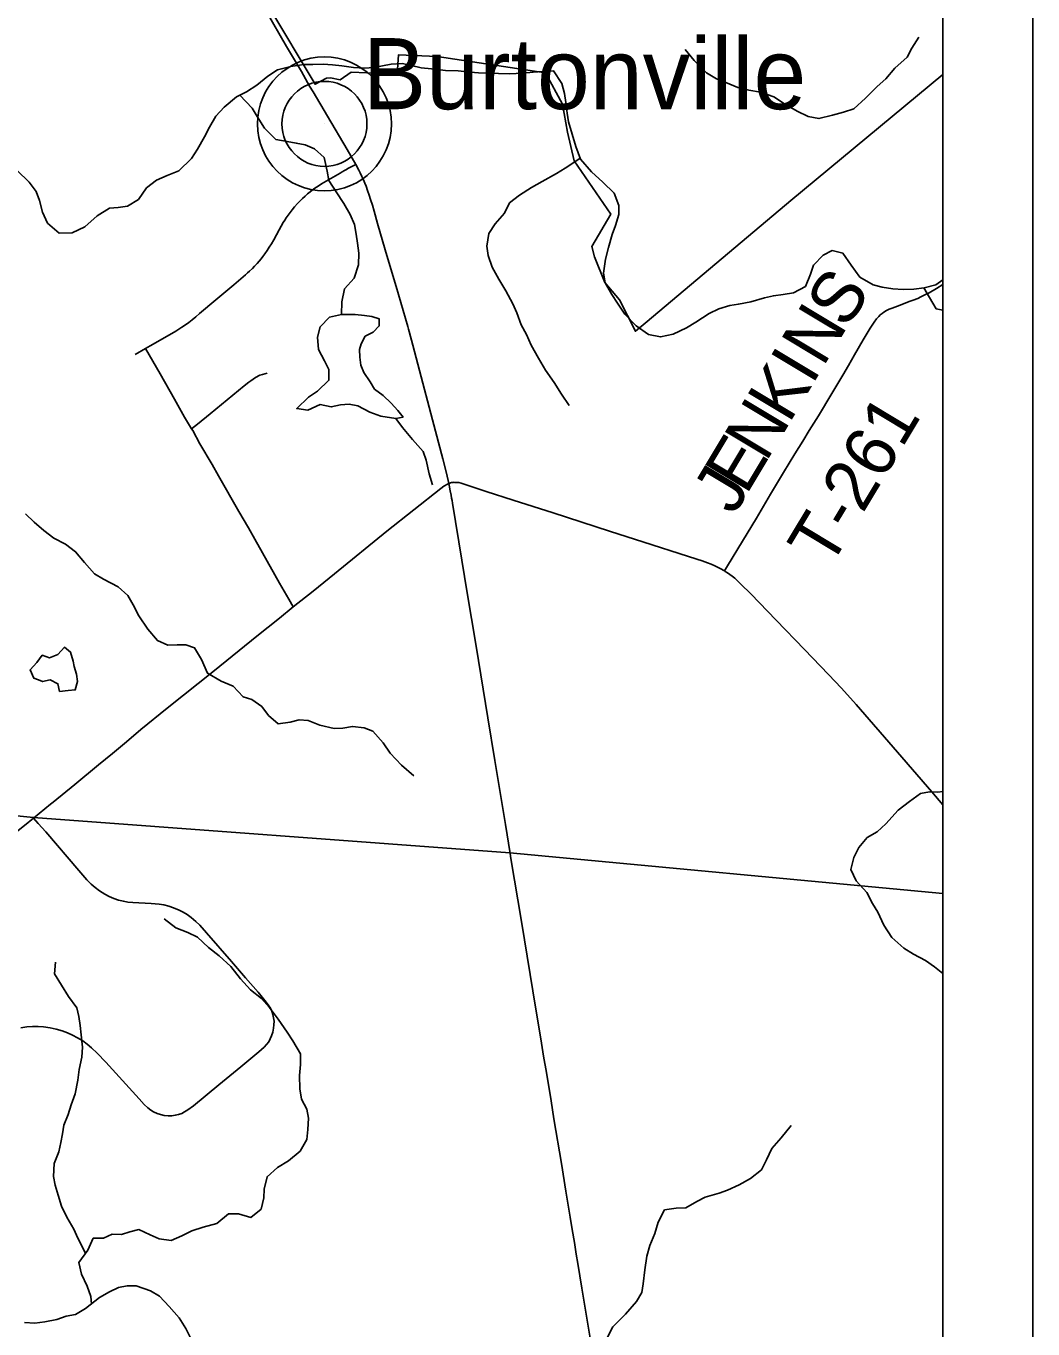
# Model space of a CAD drawing. Extents: x 0 to 34, y 0 to 22.
# Drawn here: x 7.881 to 9, y 18.658 to 20.107 of the extents above; entities that cross this region are included whole.
import ezdxf

# ---------------------------------------------------------------- set-up
doc = ezdxf.new("R2010")
doc.units = 0
for name, color, linetype in [('Default', 7, 'Continuous'), ('GM_X_County_Road', 7, 'Continuous'), ('GM_X_Major_River', 7, 'Continuous'), ('GM_X_Minor_Lake', 7, 'Continuous'), ('GM_X_Minor_River', 7, 'Continuous'), ('GM_X_State_Route', 7, 'Continuous'), ('GM_X_Township_Road', 7, 'Continuous'), ('GM_X_Township_Road_Text', 7, 'Continuous'), ('GM_X_Unincorporated', 7, 'Continuous'), ('GM_X_Unincorporated_Location', 7, 'Continuous'), ('GM_X_Unincorporated_Text', 7, 'Continuous'), ('SH_Data', 7, 'Continuous')]:
    doc.layers.add(name, color=color, linetype=linetype)

msp = doc.modelspace()

# ---------------------------------------------------------------- linework, layer by layer
at = {"layer": 'Default'}
msp.add_lwpolyline([(8.1505, 20.1279), (8.202, 20.0419), (8.2145, 20.0487), (8.2191, 20.0491), (8.2297, 20.0468), (8.2421, 20.0552), (8.2768, 20.0539), (8.2931, 20.0532), (8.2947, 20.0744), (8.3378, 20.0728), (8.458, 20.0544), (8.4769, 20.0198), (8.4824, 19.9885), (8.4901, 19.9569), (8.5306, 19.8974), (8.5095, 19.8617), (8.5125, 19.8499), (8.5241, 19.8214), (8.5403, 19.8021), (8.5581, 19.7674), (8.571, 19.7782), (8.7307, 19.9126), (8.9, 20.0527), (8.9, 20.9)], dxfattribs=at)
at = {"layer": 'GM_X_County_Road'}
for points in [[(8.657, 19.5011), (8.6524, 19.5037), (8.6494, 19.5051), (8.6462, 19.5067), (8.6422, 19.5083), (8.6381, 19.51), (8.6321, 19.5121), (8.6264, 19.5141), (8.6069, 19.5204), (8.5767, 19.5301), (8.5294, 19.5453), (8.4667, 19.5654), (8.4223, 19.5797), (8.3921, 19.5893), (8.3643, 19.5985), (8.3619, 19.5991), (8.3599, 19.5993), (8.3575, 19.5994), (8.3565, 19.5995), (8.3554, 19.5994), (8.3536, 19.5992), (8.3505, 19.5982)], [(8.9, 19.2409), (8.8876, 19.2553), (8.8493, 19.2994), (8.8033, 19.3524), (8.7871, 19.3705), (8.7727, 19.386), (8.7461, 19.4138), (8.7144, 19.4463), (8.6864, 19.4754), (8.6754, 19.4864), (8.6717, 19.4898), (8.6685, 19.4928), (8.6656, 19.4951), (8.6631, 19.497), (8.6605, 19.4988), (8.6579, 19.5005), (8.657, 19.5011)]]:
    msp.add_lwpolyline(points, dxfattribs=at)
at = {"layer": 'GM_X_Major_River'}
for points in [[(7.8707, 19.9461), (7.8841, 19.9329), (7.8919, 19.9228), (7.8958, 19.9125), (7.8989, 19.8998), (7.9047, 19.8876), (7.9174, 19.8763), (7.9318, 19.8767), (7.946, 19.8833), (7.9596, 19.8955), (7.9734, 19.904), (7.9829, 19.9049), (7.9936, 19.9062), (8.0055, 19.9139), (8.0145, 19.9267), (8.0257, 19.9352), (8.0376, 19.9406), (8.0506, 19.9457), (8.0646, 19.9595), (8.0713, 19.9696), (8.0792, 19.9835), (8.0847, 19.994), (8.0918, 20.0064), (8.1008, 20.0165), (8.1147, 20.028), (8.1258, 20.0334), (8.1374, 20.0408), (8.1494, 20.0508), (8.1601, 20.0578), (8.175, 20.0617), (8.1895, 20.0637), (8.1994, 20.0638), (8.2108, 20.064), (8.2214, 20.0634), (8.2316, 20.0624), (8.2448, 20.0606), (8.2573, 20.0596), (8.2669, 20.0605), (8.2768, 20.0622), (8.2867, 20.0643), (8.2988, 20.0648), (8.309, 20.0627), (8.32, 20.0601), (8.3313, 20.0588), (8.3469, 20.0573), (8.3609, 20.0566), (8.3708, 20.0557), (8.3836, 20.0546), (8.3935, 20.054), (8.4182, 20.0535), (8.433, 20.054), (8.4444, 20.0552), (8.4547, 20.0562), (8.4672, 20.0567), (8.4764, 20.0428), (8.4792, 20.0317), (8.4808, 20.0214), (8.4821, 20.0096), (8.4838, 20), (8.4877, 19.9863), (8.4919, 19.9725), (8.4969, 19.9587), (8.5091, 19.9444), (8.5218, 19.9331), (8.5344, 19.9207), (8.5398, 19.9072), (8.5396, 19.897), (8.5359, 19.8849), (8.5323, 19.8747), (8.5282, 19.8603), (8.5249, 19.8475), (8.5226, 19.832), (8.5243, 19.8213), (8.532, 19.8082)], [(8.532, 19.8082), (8.5382, 19.7986), (8.5463, 19.7862), (8.5589, 19.7734), (8.5728, 19.7636), (8.586, 19.761), (8.6001, 19.7642), (8.6147, 19.7711), (8.6251, 19.7773), (8.6401, 19.7869), (8.6508, 19.7924), (8.663, 19.7959), (8.6726, 19.7976), (8.6863, 19.8), (8.7016, 19.8046), (8.7115, 19.8067), (8.7225, 19.8083), (8.7339, 19.81), (8.747, 19.817), (8.7526, 19.8309), (8.7559, 19.8407), (8.7668, 19.8519), (8.7767, 19.857), (8.7888, 19.8541), (8.798, 19.8406), (8.8076, 19.8275), (8.8222, 19.8188), (8.8324, 19.8163), (8.8441, 19.8145), (8.8559, 19.8139), (8.8676, 19.814), (8.8791, 19.8157), (8.892, 19.8188), (8.9, 19.8243)]]:
    msp.add_lwpolyline(points, dxfattribs=at)
at = {"layer": 'GM_X_Minor_Lake'}
for points in [[(8.2314, 19.786), (8.2181, 19.7831), (8.2078, 19.7722), (8.2046, 19.7608), (8.2059, 19.7471), (8.2126, 19.7345), (8.2171, 19.725), (8.2173, 19.7128), (8.2046, 19.7008), (8.1947, 19.6941), (8.1816, 19.6813), (8.1938, 19.6797), (8.2075, 19.686), (8.22, 19.6832), (8.2303, 19.6857), (8.2398, 19.6863), (8.2496, 19.6843), (8.2628, 19.6773), (8.2749, 19.673), (8.2916, 19.6702)], [(8.2916, 19.6702), (8.2999, 19.672), (8.294, 19.6793), (8.2865, 19.6873), (8.2778, 19.6958), (8.2681, 19.7031), (8.2632, 19.7112), (8.2561, 19.7215), (8.2528, 19.7295), (8.2518, 19.7386), (8.2515, 19.747), (8.2531, 19.7534), (8.2577, 19.7617), (8.2665, 19.7662), (8.2734, 19.7733), (8.2732, 19.7813), (8.2652, 19.7837), (8.2569, 19.7849), (8.2466, 19.7858), (8.2314, 19.786)], [(7.9341, 19.3947), (7.9331, 19.4008), (7.9302, 19.4107), (7.9234, 19.4161), (7.9161, 19.4082), (7.9069, 19.4045), (7.8986, 19.4073), (7.8928, 19.3993), (7.8851, 19.3911), (7.8892, 19.3819), (7.8946, 19.3798)], [(7.8946, 19.3798), (7.899, 19.378), (7.9074, 19.3798), (7.9161, 19.3755), (7.9179, 19.3671), (7.9274, 19.3682), (7.9353, 19.3688), (7.9377, 19.3779), (7.9367, 19.3863), (7.9341, 19.3947)]]:
    msp.add_lwpolyline(points, dxfattribs=at)
at = {"layer": 'GM_X_Minor_River'}
for points in [[(8.8732, 20.0941), (8.8655, 20.0818), (8.8601, 20.072), (8.8466, 20.0596), (8.8366, 20.048), (8.827, 20.0393), (8.814, 20.0262), (8.8009, 20.0146), (8.7895, 20.0109), (8.7773, 20.0076), (8.7621, 20.0036), (8.7503, 20.006), (8.7379, 20.0119), (8.7239, 20.02), (8.7119, 20.0278), (8.6971, 20.0329), (8.6842, 20.0353), (8.6721, 20.0381), (8.6585, 20.0439), (8.6483, 20.0479), (8.637, 20.0544), (8.6235, 20.0683), (8.6134, 20.0805)], [(8.1183, 20.0298), (8.1321, 20.0154), (8.1377, 20.0059), (8.1459, 19.9932), (8.1582, 19.9805), (8.1711, 19.9781), (8.181, 19.9765), (8.1908, 19.9745), (8.2014, 19.9702), (8.2119, 19.9606), (8.2155, 19.9453), (8.2173, 19.935), (8.2255, 19.9224), (8.2341, 19.9094), (8.2411, 19.8972), (8.2459, 19.8861), (8.2477, 19.8754), (8.2491, 19.8652), (8.2505, 19.8541), (8.2503, 19.8412), (8.2456, 19.8265), (8.2348, 19.8144), (8.2316, 19.8), (8.2314, 19.786)], [(8.4966, 19.9597), (8.4897, 19.9547), (8.4801, 19.9484), (8.4702, 19.9428), (8.4545, 19.9338), (8.4427, 19.9271), (8.4293, 19.9186), (8.4182, 19.9099), (8.4127, 19.8986), (8.4023, 19.8866), (8.395, 19.876), (8.3929, 19.862), (8.3943, 19.8517), (8.3987, 19.8384), (8.4062, 19.8254), (8.414, 19.8124), (8.4218, 19.7978), (8.4262, 19.7879), (8.431, 19.7746), (8.4369, 19.7639), (8.4421, 19.752), (8.4503, 19.7375), (8.4581, 19.7241), (8.4678, 19.7103), (8.476, 19.6973), (8.4846, 19.6847)], [(8.8786, 19.8156), (8.885, 19.8047), (8.8924, 19.7924), (8.9, 19.7908)], [(8.2916, 19.6702), (8.299, 19.6602), (8.3103, 19.6472), (8.3223, 19.6337), (8.3256, 19.6242), (8.3288, 19.609), (8.3325, 19.5968)], [(7.88, 19.5644), (7.8897, 19.5551), (7.9003, 19.5459), (7.9115, 19.5374), (7.9244, 19.5308), (7.9357, 19.5223), (7.9458, 19.5104), (7.9566, 19.4978), (7.9668, 19.4919), (7.983, 19.4834), (7.9939, 19.4738), (7.9999, 19.4631), (8.0062, 19.4512), (8.0159, 19.4363), (8.0267, 19.4236), (8.0384, 19.4186), (8.0487, 19.4188), (8.0582, 19.4187), (8.068, 19.4156), (8.0758, 19.4026), (8.0825, 19.3873), (8.0975, 19.3784), (8.1111, 19.3729), (8.122, 19.361), (8.1318, 19.3579), (8.1428, 19.3501), (8.1502, 19.3402), (8.1608, 19.3309), (8.1744, 19.3327), (8.1843, 19.3356), (8.1942, 19.3347), (8.2074, 19.3296), (8.2233, 19.326), (8.2328, 19.3263), (8.2435, 19.3281), (8.2564, 19.3264), (8.2662, 19.3229), (8.2778, 19.3098), (8.2853, 19.2984), (8.298, 19.2849), (8.3119, 19.2734)], [(8.9, 19.2557), (8.8944, 19.2549), (8.8849, 19.2554), (8.875, 19.2536), (8.8627, 19.2446), (8.8501, 19.2349), (8.8366, 19.2198), (8.827, 19.2108), (8.8156, 19.2045), (8.8063, 19.1936), (8.8009, 19.1823), (8.7977, 19.169), (8.8036, 19.1564), (8.8152, 19.1437), (8.8215, 19.1315), (8.8275, 19.1216), (8.8341, 19.1074), (8.8431, 19.0936), (8.8566, 19.0817), (8.8672, 19.0751), (8.8804, 19.0681), (8.8905, 19.0608), (8.9, 19.0536)], [(7.9535, 18.6865), (7.9527, 18.6944), (7.9487, 18.7062), (7.9424, 18.7192), (7.9392, 18.7325), (7.9492, 18.7461), (7.9554, 18.7593), (7.9668, 18.7592), (7.9764, 18.764), (7.9866, 18.7635), (7.9961, 18.7664), (8.006, 18.769), (8.0185, 18.7631), (8.0287, 18.7588), (8.0419, 18.7568), (8.0538, 18.762), (8.0648, 18.7675), (8.0774, 18.7716), (8.0926, 18.7756), (8.1057, 18.7864), (8.1167, 18.7863), (8.1307, 18.7824), (8.1422, 18.7917), (8.145, 18.8042), (8.1455, 18.8137), (8.1487, 18.8277), (8.1602, 18.8379), (8.1724, 18.8453), (8.1855, 18.8562), (8.1928, 18.869), (8.1941, 18.88), (8.1946, 18.8929), (8.1929, 18.9028), (8.1869, 18.9139), (8.1851, 18.9253), (8.1846, 18.9402), (8.1858, 18.9523), (8.1856, 18.9641), (8.1771, 18.9786), (8.1711, 18.9885), (8.161, 19.0027), (8.1509, 19.0161), (8.1423, 19.0257), (8.1303, 19.0354), (8.119, 19.0476), (8.1082, 19.0614), (8.0954, 19.073), (8.0834, 19.0826), (8.0714, 19.0938), (8.0604, 19.0992), (8.0472, 19.1043), (8.0344, 19.1143)], [(7.9466, 18.7426), (7.9383, 18.7595), (7.9339, 18.7694), (7.9261, 18.7828), (7.9202, 18.795), (7.9165, 18.8072), (7.9132, 18.8183), (7.9111, 18.8278), (7.912, 18.8422), (7.9171, 18.8555), (7.9195, 18.8657), (7.9211, 18.8752), (7.9228, 18.885), (7.9274, 18.8968), (7.931, 18.9074), (7.9353, 18.9198), (7.9381, 18.935), (7.9398, 18.9468), (7.9426, 18.9604), (7.9435, 18.9718), (7.9418, 18.9855), (7.9408, 18.9957), (7.9394, 19.0056), (7.9372, 19.0152), (7.9279, 19.0278), (7.9122, 19.0531), (7.9135, 19.066)], [(8.5257, 18.6464), (8.5331, 18.6607), (8.5469, 18.675), (8.5593, 18.6889), (8.5651, 18.6991), (8.5667, 18.7086), (8.5684, 18.7242), (8.5709, 18.7393), (8.5741, 18.7514), (8.5795, 18.7647), (8.5835, 18.7772), (8.5905, 18.7908), (8.6034, 18.7929), (8.614, 18.7931), (8.6263, 18.8002), (8.6358, 18.805), (8.651, 18.8094), (8.6606, 18.8127), (8.6735, 18.8187), (8.6862, 18.8257), (8.6984, 18.8355), (8.7039, 18.8464), (8.7097, 18.8589), (8.7201, 18.8709), (8.7313, 18.8845)], [(7.8791, 18.6656), (7.8905, 18.6651), (7.9015, 18.6665), (7.9149, 18.669), (7.9252, 18.6727), (7.9358, 18.6744), (7.9469, 18.6811), (7.9622, 18.6935), (7.9733, 18.6998), (7.9836, 18.7047), (7.9931, 18.7064), (8.003, 18.7063), (8.0189, 18.7008), (8.0291, 18.695), (8.0399, 18.6835), (8.0508, 18.6708), (8.0582, 18.659), (8.0638, 18.6479)]]:
    msp.add_lwpolyline(points, dxfattribs=at)
at = {"layer": 'GM_X_State_Route'}
for points in [[(8.3505, 19.5982), (8.348, 19.6095), (8.344, 19.6257), (8.3326, 19.669), (8.318, 19.7236), (8.3106, 19.7519), (8.3066, 19.767), (8.3059, 19.7698), (8.3051, 19.7727), (8.292, 19.8169), (8.2863, 19.8366), (8.2799, 19.858), (8.2715, 19.8872), (8.2676, 19.9009), (8.2657, 19.9073), (8.2637, 19.9136), (8.2621, 19.9187), (8.2603, 19.9239), (8.2586, 19.9286), (8.2573, 19.932), (8.2559, 19.9355), (8.2541, 19.9393), (8.2522, 19.9433), (8.2506, 19.9462), (8.2471, 19.9527), (8.2377, 19.9693), (8.2159, 20.0062), (8.1997, 20.0334), (8.1959, 20.0399), (8.1867, 20.056), (8.1702, 20.0838), (8.1475, 20.1231)], [(8.4188, 19.187), (8.4137, 19.2193), (8.4018, 19.2904), (8.394, 19.3376), (8.3809, 19.4173), (8.3758, 19.4479), (8.371, 19.4767), (8.3651, 19.5129), (8.3547, 19.5762), (8.3543, 19.5791), (8.3537, 19.582), (8.3531, 19.5853), (8.3521, 19.5901), (8.351, 19.5962), (8.3505, 19.5982)], [(8.5112, 18.6284), (8.4985, 18.7037), (8.4962, 18.7175), (8.4939, 18.7313), (8.4922, 18.7417), (8.4902, 18.7545), (8.4879, 18.7689), (8.4857, 18.7828), (8.4808, 18.8116), (8.4759, 18.8422), (8.4674, 18.8919), (8.4643, 18.9121), (8.4591, 18.9434), (8.456, 18.9618), (8.4529, 18.9808), (8.4473, 19.0139), (8.4313, 19.1114), (8.4197, 19.1812), (8.4188, 19.187)]]:
    msp.add_lwpolyline(points, dxfattribs=at)
at = {"layer": 'GM_X_Township_Road'}
msp.add_line((8.0018, 19.7416), (8.0135, 19.7482), dxfattribs=at)
msp.add_lwpolyline([(8.9, 19.1426), (8.9, 20.9), (4.4664, 20.9), (4.4684, 20.7448), (4.4849, 19.6021), (5.1411, 19.5203), (5.6889, 19.4592), (5.8809, 19.4409), (6.3561, 19.3959), (7.1834, 19.2978), (7.8888, 19.2268), (8.4186, 19.1875)], close=True, dxfattribs=at)
for points in [[(8.0135, 19.7482), (8.0186, 19.751), (8.0348, 19.7602), (8.0472, 19.7674), (8.0507, 19.7696), (8.054, 19.7718), (8.057, 19.7739), (8.0616, 19.7772), (8.0653, 19.7802), (8.0694, 19.7834), (8.0735, 19.7869), (8.0917, 19.8023), (8.1117, 19.819), (8.1245, 19.83), (8.1268, 19.8322), (8.1291, 19.8342), (8.1323, 19.8372), (8.1348, 19.8398), (8.1375, 19.8426), (8.1397, 19.8451), (8.142, 19.8478), (8.1438, 19.8503), (8.1461, 19.8533), (8.1486, 19.857), (8.151, 19.8606), (8.1534, 19.8646), (8.1561, 19.8691), (8.1621, 19.8801), (8.1666, 19.8882), (8.1682, 19.8907), (8.1699, 19.8934), (8.172, 19.8963), (8.1742, 19.8994), (8.1765, 19.9022), (8.1792, 19.9056), (8.1825, 19.9092), (8.1851, 19.912), (8.1879, 19.9148), (8.1908, 19.9176), (8.1934, 19.9199), (8.1964, 19.9224), (8.1989, 19.9243), (8.2018, 19.9265), (8.2053, 19.9287), (8.2091, 19.9312), (8.2298, 19.9432), (8.2321, 19.9446), (8.2347, 19.946), (8.2362, 19.9468), (8.2392, 19.9484), (8.2471, 19.9527)], [(8.657, 19.5011), (8.6604, 19.5066), (8.6773, 19.534), (8.6925, 19.5597), (8.7084, 19.5864), (8.7228, 19.6103), (8.7354, 19.631), (8.7441, 19.6453), (8.7514, 19.6569), (8.7615, 19.6733), (8.7766, 19.6982), (8.7887, 19.7185), (8.795, 19.7293), (8.8017, 19.7412), (8.8114, 19.7578), (8.8191, 19.7706), (8.8235, 19.7774), (8.8261, 19.781), (8.8285, 19.7839), (8.8303, 19.7857), (8.8323, 19.7872), (8.8344, 19.7887), (8.8372, 19.7903), (8.8402, 19.7917), (8.8435, 19.7931), (8.8525, 19.7965), (8.8624, 19.8003), (8.867, 19.8019), (8.8719, 19.8039), (8.8755, 19.8055), (8.8799, 19.8077), (8.8848, 19.8102), (8.8928, 19.8149), (8.9, 19.8194)], [(8.0647, 19.659), (8.057, 19.6719), (8.0457, 19.6919), (8.0297, 19.72), (8.0176, 19.741), (8.0135, 19.7482)], [(8.0647, 19.659), (8.0713, 19.6642), (8.0854, 19.6754), (8.1232, 19.7067), (8.1282, 19.7106), (8.1306, 19.7123), (8.133, 19.714), (8.1357, 19.7158), (8.1372, 19.7167), (8.1389, 19.7176), (8.1406, 19.7184), (8.1436, 19.7194), (8.1486, 19.7209)], [(8.1776, 19.461), (8.1727, 19.4694), (8.1624, 19.4874), (8.1434, 19.5209), (8.135, 19.5361), (8.1281, 19.5487), (8.1174, 19.5669), (8.0945, 19.6068), (8.0874, 19.6191), (8.074, 19.6423), (8.0659, 19.6569), (8.0647, 19.659)], [(8.9, 16.5763), (8.9, 19.1426), (8.4186, 19.1875), (7.8888, 19.2268), (7.1834, 19.2978), (6.3561, 19.3959), (5.8809, 19.4409), (5.6889, 19.4592), (5.1411, 19.5203), (4.4849, 19.6021), (4.4789, 19.5742), (4.3389, 18.9527), (4.2897, 18.7747), (4.1943, 18.4289), (4.1901, 18.4135), (4.0744, 17.9948), (3.9903, 17.6899), (3.7921, 17.074)], [(8.1776, 19.461), (8.1997, 19.4786), (8.2234, 19.4978), (8.2818, 19.545), (8.3417, 19.5927), (8.3451, 19.595), (8.349, 19.5974), (8.3505, 19.5982)], [(7.8891, 19.2262), (7.8954, 19.2313), (7.9077, 19.2416), (7.9107, 19.244), (7.9348, 19.2635), (7.9611, 19.2853), (7.9766, 19.2979), (7.9922, 19.3111), (8.0084, 19.3246), (8.0377, 19.3485), (8.09, 19.3904), (8.1374, 19.4284), (8.1625, 19.4486), (8.1776, 19.461)], [(7.6938, 19.0676), (7.7079, 19.0789), (7.7357, 19.1017), (7.7526, 19.1155), (7.7776, 19.1359), (7.8514, 19.1958), (7.8736, 19.2138), (7.8789, 19.218), (7.8891, 19.2262)], [(7.8749, 18.9932), (7.8816, 18.9941), (7.8878, 18.9945), (7.894, 18.9945), (7.9002, 18.9941), (7.9076, 18.993), (7.9143, 18.9916), (7.9209, 18.9897), (7.9267, 18.9876), (7.9324, 18.9851), (7.9379, 18.9822), (7.9437, 18.9786), (7.9487, 18.975), (7.9535, 18.9711), (7.9598, 18.965), (7.9692, 18.9551), (8.0063, 18.9141), (8.0118, 18.9081), (8.0159, 18.9043), (8.0193, 18.9016), (8.0224, 18.8997), (8.0264, 18.8979), (8.03, 18.8968), (8.0342, 18.8959), (8.0385, 18.8955), (8.0429, 18.8955), (8.0466, 18.896), (8.0502, 18.8968), (8.0537, 18.8981), (8.057, 18.8997), (8.0607, 18.9021), (8.0667, 18.9066), (8.0949, 18.9299), (8.1195, 18.9499), (8.1396, 18.9665), (8.1452, 18.9715), (8.1481, 18.9746), (8.1504, 18.9776), (8.1522, 18.9809), (8.1537, 18.9843), (8.155, 18.9884), (8.1559, 18.9927), (8.1563, 18.9964), (8.1564, 19.0007), (8.1559, 19.0044), (8.1551, 19.008), (8.1539, 19.0116), (8.1523, 19.0149), (8.15, 19.0186), (8.1463, 19.0236), (8.1387, 19.0327), (8.1248, 19.0486), (8.1089, 19.0668), (8.0812, 19.0987), (8.0738, 19.1071), (8.0693, 19.1114), (8.0642, 19.1159), (8.0597, 19.1192), (8.0555, 19.1218), (8.051, 19.1241), (8.0447, 19.1267), (8.0394, 19.1285), (8.034, 19.1298), (8.0285, 19.1307), (8.0198, 19.1314), (7.9993, 19.1324), (7.9938, 19.1329), (7.9889, 19.1338), (7.9835, 19.1352), (7.9782, 19.1369), (7.973, 19.1391), (7.9681, 19.1417), (7.9623, 19.1454), (7.9574, 19.1491), (7.9532, 19.1528), (7.9483, 19.1577), (7.9392, 19.1679), (7.9025, 19.2108), (7.8943, 19.2202), (7.8891, 19.2262)]]:
    msp.add_lwpolyline(points, dxfattribs=at)
at = {"layer": 'GM_X_Unincorporated'}
for radius in [0.0744, 0.0472]:
    msp.add_circle((8.2124, 19.9978), radius, dxfattribs=at)
at = {"layer": 'GM_X_Unincorporated_Location'}
msp.add_line((8.2124, 19.9978), (8.2124, 19.9978), dxfattribs=at)
at = {"layer": 'SH_Data'}
for p, q in [((9, 21), (9, 14)), ((8.9, 20.9), (8.9, 14.1))]:
    msp.add_line(p, q, dxfattribs=at)

# ---------------------------------------------------------------- texts
at = {"layer": 'GM_X_Township_Road_Text'}
for s, height, rotation, p in [('S', 0.0568, 55.6682, (8.7919, 19.7687)), ('N', 0.0568, 58.9894, (8.7666, 19.7266)), ('I', 0.0568, 59.0255, (8.7546, 19.7066)), ('K', 0.0568, 59.0387, (8.7289, 19.6638)), ('N', 0.0568, 59.0381, (8.7032, 19.6209)), ('T-261', 0.05682, 58.99, (8.7738, 19.5025)), ('E', 0.0568, 59.0351, (8.6813, 19.5844)), ('J', 0.0568, 59.0351, (8.6676, 19.5616))]:
    msp.add_text(s, height=height, rotation=rotation, dxfattribs=at).set_placement(p)
at = {"layer": 'GM_X_Unincorporated_Text'}
msp.add_text('Burtonville', height=0.078977, rotation=0, dxfattribs=at).set_placement((8.255, 20.0141))

doc.saveas('drawing.dxf')
